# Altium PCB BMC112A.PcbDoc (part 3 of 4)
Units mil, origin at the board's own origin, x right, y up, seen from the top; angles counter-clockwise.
Board outline 5600 x 6100 mil, 8 copper layers (Top Layer, Signal Layer 1, Signal Layer 2, Signal Layer 3, Signal Layer 4, Signal Layer 5, Signal Layer 6, Bottom Layer), stack 62.048 mil thick; 366 components, 158 nets, 872 pads, 1045 vias.
Unrouted connection lines stored in the file: 4.
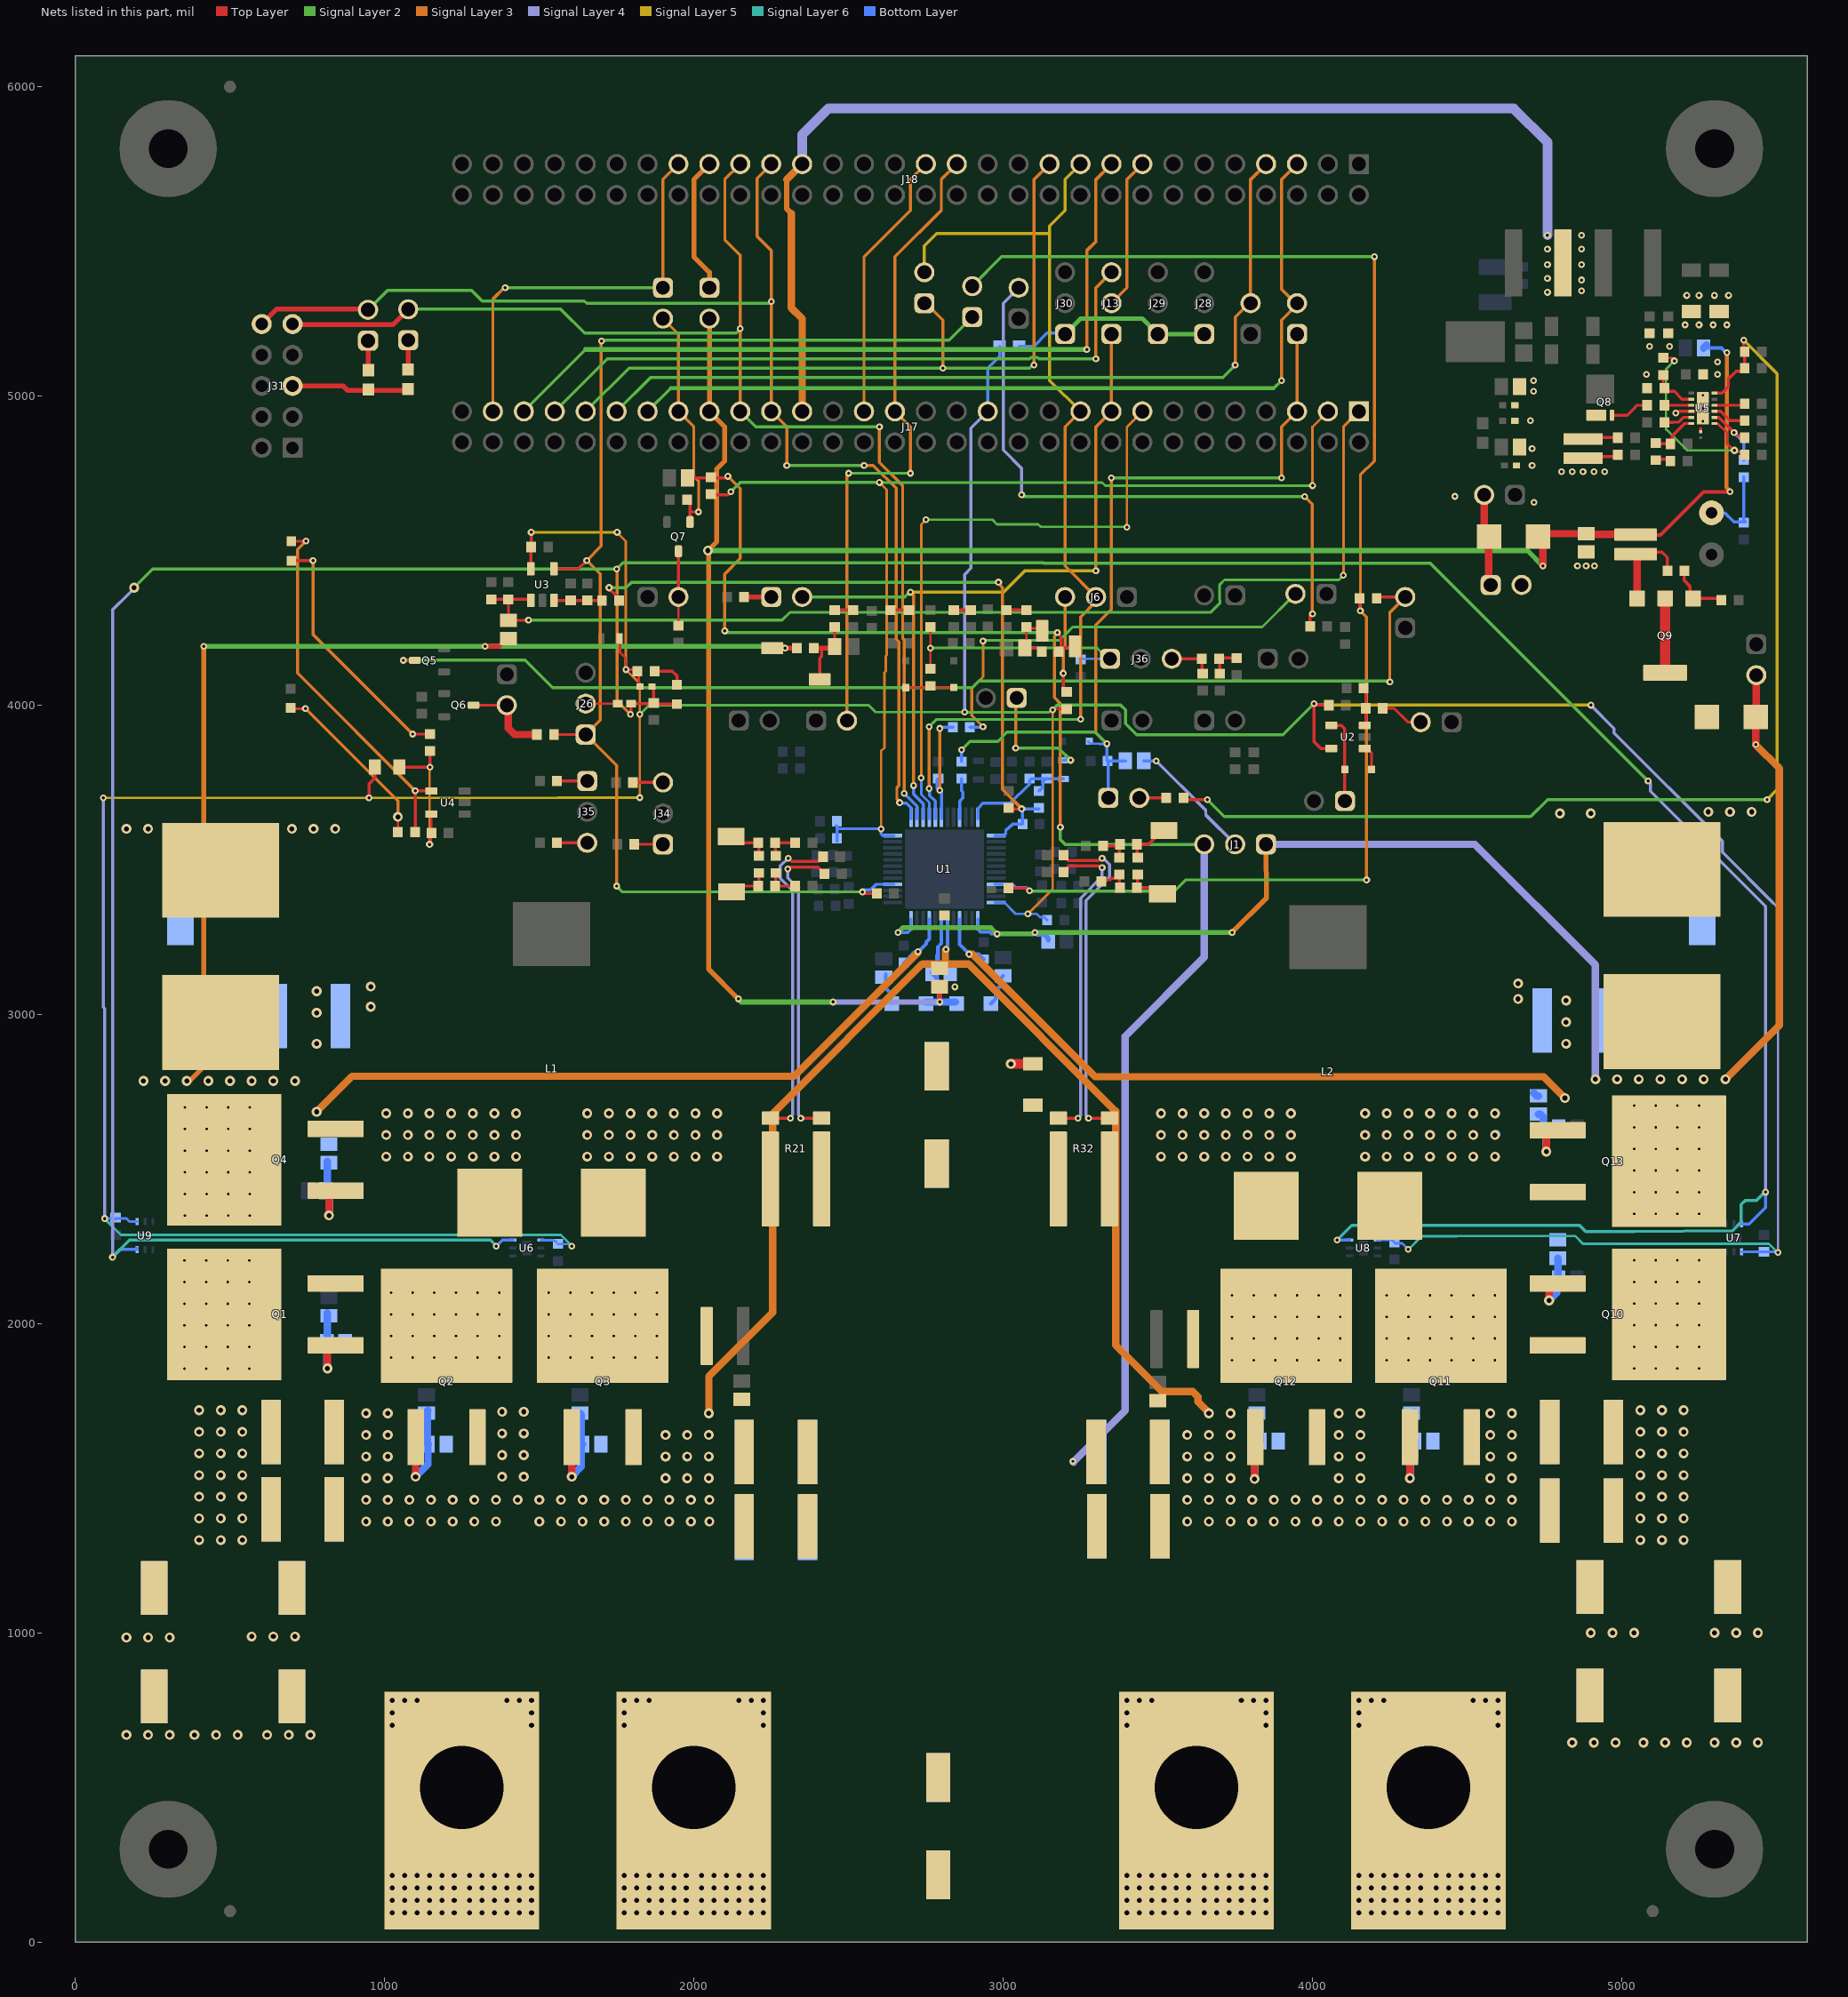
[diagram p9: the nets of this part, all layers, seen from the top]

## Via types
v1: diameter 32, hole 16, Top Layer to Bottom Layer, tented both sides, 330 vias
v2: diameter 32, hole 16, Top Layer to Bottom Layer, 240 vias
v3: diameter 22, hole 10, Top Layer to Bottom Layer, tented both sides, 222 vias
v4: diameter 24, hole 8, Top Layer to Bottom Layer, 192 vias
v5: diameter 19.68, hole 7.87, Top Layer to Bottom Layer, tented both sides, 36 vias
v6: diameter 24, hole 8, Top Layer to Bottom Layer, tented both sides, 14 vias
v7: diameter 24, hole 10, Top Layer to Bottom Layer, tented both sides, 7 vias
v8: diameter 19.68, hole 7.87, Top Layer to Bottom Layer, 3 vias
v9: diameter 22, hole 8, Top Layer to Bottom Layer, tented both sides, 1 vias

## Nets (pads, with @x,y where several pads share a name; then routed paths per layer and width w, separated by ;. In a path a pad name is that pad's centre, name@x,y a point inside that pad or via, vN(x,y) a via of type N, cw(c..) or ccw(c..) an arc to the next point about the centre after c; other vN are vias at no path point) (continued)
NetC76_1: C76.1 R62.1 R69.2 U5.12 | length 3720.2
  Top Layer w9.8: R62.1@3582.56,3700 3587.56,3695 v3(3660,3695) ; U5.12@5299.8,5009.37 5324.37,5009.37 5345,5030 5345,5055 5370,5080 C76.1@5397.44,5080 ; v3(5395,5180) 5395,5141.83 5396.83,5140 R69.2@5400,5140 ; C76.1@5397.44,5077.56 R69.2@5397.44,5130
  Signal Layer 2 w9.8: v3(3660,3695) 3715,3640 4705.47,3640 4760.47,3695 v3(5470,3695)
  Signal Layer 5 w9.8: v3@5391.62,5182.78 5502.5,5071.9 5502.5,3727.5 v3(5470,3695)
NetC77_1: C77.1 U5.9 | length 102.8
  Top Layer w9.8: U5.9@5299.82,4950.29 5319.7,4950.29 5349.99,4920 C77.1@5390,4920
NetC78_1: C78.1 C79.1 U5.6 | length 143.7
  Top Layer w9.8: C78.1@5120,4845 C79.1@5157.44,4845 5163.73,4851.29 5163.73,4870.69 5203.98,4910.94 U5.6@5225,4910.94
NetC78_2: C78.2 R70.2 | length 59.5
  Top Layer w9.8: C78.2@5105,4795 5157.44,4795 R70.2@5152.44,4790
NetC81_1: C81.1 R73.2 | length 61
  Top Layer w10: C81.1@2455,4310 2457.44,4307.56 R73.2@2515,4307.56
NetC81_2: C81.2 R75.2 R77.1 TP2.1 | length 230.5
  Top Layer w8: C81.2@2455,4250 2455,4190.47 R75.2@2455.47,4190
  Top Layer w10: TP2.1@2406.59,4083.27 2406.59,4151.55 2413.31,4158.27 2413.31,4182.03 2416.28,4185
  Top Layer w16: R77.1@2387.56,4185 2416.28,4185 2445,4185 R75.2@2450,4180
NetC82_1: C82.1 R76.1 R78.2 TP3.1 | length 188.7
  Top Layer w8: R76.1@3069.53,4185 3075,4190.47 C82.1@3075,4245 ; C82.1@3075,4252.44 3079.13,4248.31 TP3.1@3137.24,4248.31
  Top Layer w10: R76.1@3070,4185 R78.2@3132.44,4185
NetC82_2: C82.2 R74.1 | length 61.1
  Top Layer w10: R74.1@3010,4307.56 3067.44,4307.56 C82.2@3070,4305
NetC85_1: C85.1 CS1B.1 R93.2 | length 155.2
  Top Layer w10: CS1B.1@2115,3390 2140,3415 R93.2@2207.44,3415 ; R93.2@2210,3405 C85.1@2210,3457.44
NetC85_2: C85.2 CS1A.1 R82.2 | length 135.2
  Top Layer w10: CS1A.1@2120,3575 2140,3555 R82.2@2207.44,3555 ; C85.2@2210,3512.56 2210,3545 R82.2@2215,3550
NetC86_2: C86.2 R83.1 | length 56
  Top Layer w10: R83.1@2640,4310 2642.44,4307.56 C86.2@2695,4307.56
NetC87_2: C87.2 R84.1 | length 56
  Top Layer w12: C87.2@2840,4307.56 2892.56,4307.56 R84.1@2895,4310
NetC88_1: C88.1 R85.1 R92.2 | length 95.5
  Top Layer w10: C88.1@3700,4102.56 3700,4140 R85.1@3705,4145 ; R85.1@3700,4155 3702.44,4152.56 R92.2@3750,4152.56
NetC91_1: C91.1 R89.2 R109.2 U3.3 | length 155.6
  Top Layer w10: U3.3@1547.4,4338.82 1601.4,4338.82 R109.2@1601.63,4338.59 C91.1@1654.93,4338.59 1702.54,4338.59 R89.2@1702.83,4338.3
NetC95_1: C95.1 R87.1 U2.3 | length 114.2
  Top Layer w9: R87.1@4172.44,3990 C95.1@4172.44,4047.56
  Top Layer w10: U2.3@4169.13,3934.69 4172.44,3938 R87.1@4172.44,3990
NetC97_1: C97.1 J36.3 R85.2 | length 150.6
  Top Layer w10: J36.3@3540,4155 J36.3@3545,4150 R85.2@3642.44,4150 3642.44,4107.56 C97.1@3645,4105
NetC98_1: C98.1 CS2B.1 R95.2 | length 133.2
  Top Layer w10: R95.2@3432.56,3410 R95.2@3435,3410 ; C98.1@3435,3452.44 R95.2@3435,3410 ; CS2B.1@3515,3390 3495,3410 R95.2@3435,3410
NetC98_2: C98.2 CS2A.1 R94.2 | length 147.2
  Top Layer w10: C98.2@3435,3510 3432.56,3512.44 R94.2@3432.56,3550 3470,3550 3515.1,3595.1 CS2A.1@3519.9,3595.1 CS2A.1@3520,3595
NetC99_1: C99.1 R93.1 R97.2 | length 122
  Top Layer w10: R93.1@2262.56,3415 R93.1@2265,3415 ; C99.1@2265,3457.44 R93.1@2265,3415 ; R97.2@2340,3410 2335,3415 2332.44,3415 R93.1@2265,3415
NetC99_2: C99.2 R82.1 R96.2 | length 113
  Top Layer w10: C99.2@2270,3510 2262.56,3517.44 R82.1@2262.56,3555 R96.2@2327.44,3555
NetC100_1: C100.1 R95.1 R99.2 | length 91.1
  Top Layer w9.8: R99.2@3317.56,3430 3322.56,3435 3345,3435 3350,3440 C100.1@3360,3440 ; R95.1@3370,3410 3375,3415 C100.1@3375,3452.44
NetC100_2: C100.2 R94.1 R98.2 | length 94.9
  Top Layer w9.8: R98.2@3322.56,3545 R94.1@3375,3545 ; C100.2@3375,3507.56 R94.1@3375,3545 ; R94.1@3375,3550 R94.1@3375,3545
NetC106_1: C106.1 J36.1 R81.1 R86.2 | length 825.5
  Top Layer w8: R81.1@2765,4120 v3(2765,4185) R86.2@2765,4250
  Signal Layer 2 w8: v3(2765,4185) 3303.38,4185 3338.38,4150 J36.1@3345,4150 J36.1@3350,4150
  Bottom Layer w8: C106.1@3250,4147.6 3252.4,4150 J36.1@3345,4150
NetD1_1: D1.1 R13.2 | length 103.2
  Bottom Layer w9.8: D1.1@2637.48,3037.4 D1.1@2639.88,3035
  Bottom Layer w12: R13.2@2620,3130 2620,3085.06 2637.48,3067.58 D1.1@2637.48,3037.4
NetD2_1: D2.1 R19.2 | length 106
  Bottom Layer w12: D2.1@2960.12,3035 2974.98,3049.87 2974.98,3075.5 2990.33,3090.85 2990.33,3115.12 R19.2@2999.78,3124.57
NetD3_2: D3.2 J26.2 | length 103.3
  Top Layer w8: J26.2@1650,4005 D3.2@1753.35,4005
NetD5_2: D5.2 R42.1 | length 108.7
  Top Layer w10: R42.1@1872.56,4110 1930,4110 1945,4095 D5.2@1945,4066.5 D5.2@1945,4065
NetD6_2: D6.2 J38.2 J39.1 | length 291.8
  Top Layer w24: J38.2@4555,4680 4555,4550 D6.2@4565.63,4539.37 ; J39.1@4570,4400 4570,4543.74 D6.2@4571.26,4545
  Top Layer w32: D6.2@4575,4550 D6.2@4576.26,4550
NetD7_1: D7.1 Q9.2 Q9.4 | length 245.1
  Top Layer w32: Q9.4@5140,4100 Q9.4@5140,4104.92 Q9.2@5140,4345.08
NetD9_1: D9.1 D10.1 R81.2 | length 160
  Top Layer w8: D9.1@2685,4056.69 2770,4056.69 D10.1@2845,4056.69
NetD11_2: D11.2 R90.2 | length 566.7
  Top Layer w8: R90.2@1042.91,3589.16 v1(1042.91,3638.91)
  Top Layer w9: D11.2@700.46,3988.84 v3(743.75,3988.84)
  Signal Layer 3 w10: v3@743.87,3988.72 1042.91,3689.68 v1(1042.91,3638.91)
NetD12_1: D12.1 R90.1 U4.4 | length 1206.2
  Top Layer w9: D12.1@701.73,4530.2 701.92,4530.38 v3(745.21,4530.38)
  Top Layer w10: R90.1@1098.03,3589.16 1098.64,3589.78 v3(1098.64,3723.51) 1099.2,3722.96 1150.31,3722.96 U4.4@1150.87,3722.4
  Signal Layer 3 w10: v3(745.21,4530.38) 718.53,4503.7 718.53,4103.63 v3(1098.64,3723.51)
NetD12_2: D12.2 R91.2 | length 819.9
  Top Layer w10: D12.2@698.23,4467.2 v3(768.08,4467.2) ; v3(1090.45,3906.5) R91.2@1146.22,3906.5
  Signal Layer 3 w10: v3(768.08,4467.2) 768.08,4228.86 v3(1090.45,3906.5)
NetD13_1: D13.1 U2.1 | length 80.7
  Top Layer w10: U2.1@4169.13,3859.89 4176.26,3859.89 4191.01,3845.14 D13.1@4191.01,3792.44
NetD13_2: D13.2 J42.1 U2.4 | length 272
  Top Layer w10: U2.4@4060.87,3934.69 4093.28,3934.69 4104.4,3923.58 D13.2@4104.4,3792.44 4104.4,3700.6 J42.1@4105,3700
NetJ1_2: J1.2 R2.2 | length 416.1
  Signal Layer 4 w9.8: v3(3495,3820) 3655,3660 3655,3650
  Signal Layer 4 w10: 3655,3650 3655,3645 J1.2@3750,3550
  Bottom Layer w9.8: R2.2@3454.53,3820 v3(3495,3820)
NetJ3_2: J3.2 Q7.3 R10.1 | length 247.3
  Top Layer w8: R10.1@1950,4257.56 J3.2@1950,4345
  Top Layer w9: Q7.3@1950,4497.76 J3.2@1950,4350 1950,4345 J3.2@1955,4340
NetJ4_2: J4.2 Q6.3 R8.1 | length 282.6
  Top Layer w9.8: Q6.3@1287.24,4000 1390,4000 J4.2@1395,3995
  Top Layer w24: J4.2@1395,3995 1400,3990 1400,3925 1420,3905 R8.1@1492.44,3905
NetJ5_2: J5.2 Q5.3 R1.1 | length 3666.5
  Top Layer w9.8: v3(1060,4145) Q5.3@1097.76,4145 ; R1.1@4207.56,4345 4212.56,4350 4295,4350 J5.2@4300,4345
  Signal Layer 2 w9.8: v3(1060,4145) 1060.25,4145.25 1454.75,4145.25 1543.19,4056.81 2900.43,4056.81 2921.26,4077.64 4238.74,4077.64 4239.04,4077.33 4247.67,4077.33 v3(4250,4075)
  Signal Layer 3 w9.8: v3(4250,4075) 4250,4300 J5.2@4300,4350
NetJ6_3: J6.3 R15.1 | length 314.9
  Top Layer w10: v3(3193.83,4103.31) 3193.83,4053.31 3204.58,4042.56 R15.1@3205,4042.56
  Signal Layer 3 w10: v3(3193.83,4103.31) 3193.83,4183.19 3200,4189.36 J6.3@3200,4350
NetJ12_2: J12.2 R20.2 | length 1426.7
  Signal Layer 2 w9: v3(2935,4207.87) 2937.13,4210 3183.06,4210 3204.84,4231.78 3204.84,4232.47 3225,4252.63 3837.63,4252.63 J12.2@3945,4360
  Signal Layer 3 w9: v3(2935,3930) 2898.33,3966.67 2898.33,4055.28 2935,4091.94 v3(2935,4207.87)
  Bottom Layer w9: R20.2@2892.56,3928.94 2936.06,3928.94 v3(2935,3930)
NetJ13_2: J13.2 J18.15 | length 491.4
  Signal Layer 3 w10: J13.2@3350,5300 3400,5350 3400,5700 J18.15@3450,5750
NetJ13_3: J13.3 J17.53 | length 2125.2
  Signal Layer 2 w10: J17.53@1550,4950 1720,5120 3084.82,5120 3089.7,5124.87 3110.3,5124.87 3115.18,5120 v3(3300,5120)
  Signal Layer 3 w10: v3(3300,5120) 3300,5350 J13.3@3350,5400
NetJ14_2: J14.2 R18.1 | length 2080
  Top Layer w10: R18.1@3992.44,4255 3992.44,4289.14 3998.3,4295 v3(4000,4295)
  Signal Layer 2 w10: v3(3060,4680) 3065,4675 v3(3975,4675)
  Signal Layer 3 w10: v3(3975,4675) 3999.65,4650.35 3999.65,4295.35 v3(4000,4295)
  Signal Layer 4 w10: J14.2@3045,5365 3045,5345 3000,5300 3000,4825 3060,4765 v3(3060,4680)
NetJ16_2: J16.2 J17.31 J18.27 | length 2089
  Signal Layer 2 w9.8: v3(2500,4750) v3(2700,4750)
  Signal Layer 3 w8: J17.31@2650,4950 J17.31@2650,4960
  Signal Layer 3 w9.8: J16.2@2495,3950 2495,4745 v3(2500,4750) ; J17.31@2650,4960 2650,5450 2800,5600 2800,5700 J18.27@2850,5750 ; J17.31@2670,4940 2668.02,4938.02 2668.02,4931.98 2700,4900 v3(2700,4750)
NetJ17_33: J17.33 J18.29 | length 882.8
  Signal Layer 3 w9.8: J17.33@2550,4950 2550,5450 2700,5600 2700,5700 J18.29@2750,5750
NetJ17_47: J17.47 J18.5 J22.2 | length 2853.6
  Signal Layer 2 w10: J17.47@1850,4950 1925,5025 ; 3875,5025 v3(3900,5050)
  Signal Layer 2 w12: 1925,5025 3875,5025
  Signal Layer 3 w10: v3(3900,5050) 3900,5245 3950,5295 3900,5345 3900,5700 J18.5@3950,5750
NetJ17_49: J17.49 J18.7 J23.2 | length 2753.6
  Signal Layer 2 w10: J17.49@1750,4950 1860,5060 3710,5060 v3(3750,5100)
  Signal Layer 3 w10: v3(3750,5100) 3750,5255 3800,5305 3800,5700 J18.7@3850,5750
NetJ17_51: J17.51 J18.21 J32.1 | length 2424.8
  Signal Layer 2 w10: J17.51@1650,4950 1790,5090 v3(2805,5090) 3085,5090 v3@3100,5105
  Signal Layer 3 w10: J32.1@2745,5305 2805,5245 v3(2805,5090) ; v3(3100,5100) 3100,5700 J18.21@3150,5750
NetJ17_55: J17.55 J18.17 | length 2541
  Signal Layer 2 w10: J17.55@1450,4950 1650,5150 ; v3(3270,5150) v3@3275,5150
  Signal Layer 2 w16: 1650,5150 v3(3270,5150)
  Signal Layer 3 w10: v3(3270,5150) 3270,5470 3300,5500 3300,5700 J18.17@3350,5750
NetJ17_57: J17.57 J18.45 J20.1 | length 1349.2
  Signal Layer 2 w10: v3(1390,5350) J20.1@1900,5350
  Signal Layer 3 w9.8: J20.1@1900,5350 1900,5700 J18.45@1950,5750
  Signal Layer 3 w10: J17.57@1350,4950 1350,5313.31 1386.69,5350 v3(1390,5350)
NetJ18_43: J18.43 J19.1 | length 441.4
  Signal Layer 3 w16: J19.1@2050,5350 2050,5400 2000,5450 2000,5700 J18.43@2050,5750
NetJ25_1: J25.1 R101.1 | length 95.4
  Top Layer w16: R101.1@1075.28,5085.4 1075.84,5085.96 1075.84,5179.81 J25.1@1076.4,5180.37
NetJ27_1: J27.1 R17.1 | length 94.5
  Top Layer w10: J27.1@2245,4350 J27.1@2250,4345
  Top Layer w16: R17.1@2162.56,4350 2245,4350 J27.1@2250,4350
NetJ28_1: J28.1 J29.1 J30.1 R105.1 | length 658.7
  Signal Layer 2 w14: J30.1@3200,5200 3250,5250 3450,5250 J29.1@3500,5200 J28.1@3650,5200
  Bottom Layer w10: R105.1@3051.48,5160.84 3099.64,5160.84 3141.81,5203.01 3196.99,5203.01 J30.1@3200,5200
NetJ31_5: J31.5 R101.2 R103.2 | length 380.7
  Top Layer w16: J31.5@702.36,5032.48 865.83,5032.48 880.22,5018.09 1070.96,5018.09 R101.2@1075.28,5022.41
NetJ34_1: J34.1 R44.2 | length 92.4
  Top Layer w9.8: R44.2@1807.56,3550 J34.1@1900,3550
NetJ34_3: J34.3 R55.2 | length 104.5
  Top Layer w9.8: R55.2@1802.56,3750 J34.3@1900,3750 J34.3@1905,3745
NetJ35_1: J35.1 R47.2 | length 99.5
  Top Layer w9.8: R47.2@1557.56,3755 1650,3755 J35.1@1655,3750
NetJ35_3: J35.3 R48.2 | length 99.5
  Top Layer w9.8: R48.2@1557.56,3550 1562.56,3555 J35.3@1655,3555
NetJ37_1: J37.1 R64.1 | length 381.2
  Signal Layer 2 w10: v3(3040.15,3861.11) 3178.82,3861.11 v3(3218.11,3821.81)
  Signal Layer 3 w10: v3(3040.15,3861.11) 3040.15,4019.89 J37.1@3043.56,4023.3
  Bottom Layer w10: R64.1@3194.78,3821.81 v3(3218.11,3821.81)
NetJ40_2: J40.2 R62.2 | length 87.4
  Top Layer w9.8: J40.2@3440,3700 R62.2@3527.44,3700
NetJ43_2: J43.2 R87.2 | length 164.6
  Top Layer w9: R87.2@4227.56,3990 4264.04,3990 4309.29,3944.75 4372.2,3944.75 J43.2@4373.03,3943.92
NetJ44_1: J44.1 R103.1 | length 95.5
  Top Layer w16: J44.1@946.3,5178.58 946.88,5178 946.88,5084.16 R103.1@947.45,5083.59
NetL1_2: L1.2 R21.3 | length 0
  other v1: 1655,2540 1725,2540 1795,2540 1865,2540 1935,2540 2005,2540 2075,2540 1655,2610 1725,2610 1795,2610 1865,2610 1935,2610 2005,2610 2075,2610 1655,2680 1725,2680 1795,2680 1865,2680 1935,2680 2005,2680 2075,2680
NetL2_1: L2.1 R32.4
  other v1: 3510,2540 3580,2540 3650,2540 3720,2540 3790,2540 3860,2540 3930,2540 3510,2610 3580,2610 3650,2610 3720,2610 3790,2610 3860,2610 3930,2610 3510,2680 3580,2680 3650,2680 3720,2680 3790,2680 3860,2680 3930,2680
NetQ1_1: Q1.1 R22.2 R26.2 | length 292
  Top Layer w24: v2(815,1855) 815,1916.08 828.92,1930 Q1.1@841.63,1930
  Bottom Layer w24: R26.2@809.53,1935 R26.2@813.47,1938.94 ; v2(815,1855) 813.47,1856.53 R26.2@813.47,1938.94 ; R26.2@815,1950 R26.2@814.76,1949.76 ; R22.2@815,2035 814.76,2034.76 R26.2@814.76,1949.76 ; R26.2@813.47,1938.94 814.76,1940.24 R26.2@814.76,1949.76 ; R26.2@813.47,1938.94 813.47,1948.47 R26.2@814.76,1949.76
NetQ2_1: Q2.1 R24.1 R27.2 | length 351.3
  Top Layer w24: v2(1100,1505) Q2.1@1100,1632.64
  Bottom Layer w24: v2(1100,1505) 1140,1545 R24.1@1140,1600 ; R27.2@1140,1720 1137.74,1717.74 1137.74,1612.74 R24.1@1140.47,1610
NetQ3_1: Q3.1 R25.1 R28.2 | length 350.6
  Top Layer w24: v2@1600,1505 v2@1602.5,1507.5 ; v2(1605,1505) Q3.1@1605,1632.64
  Bottom Layer w24: v2@1602.84,1505 v2(1605,1505) 1605,1507.16 1635,1537.16 1635,1605 R25.1@1640,1610 ; R28.2@1631.77,1710.47 1636.12,1706.12 1636.12,1616.12 R25.1@1635,1615
NetQ4_1: Q4.1 R29.2 R30.2 | length 266.2
  Top Layer w24: v2(820,2350) 820,2408.37 Q4.1@841.63,2430
  Bottom Layer w24: R30.2@809.53,2430 814.76,2435.24 814.76,2524.76 R29.2@815,2525 ; v2(820,2350) R30.2@820,2430
NetQ8_1-2-3: Q8.1-2-3 R54.1 R60.2 | length 110.2
  Top Layer w9.8: R60.2@4875,4865.51 4984.49,4865.51 R54.1@4985,4865
NetQ8_4: Q8.4 R52.1 | length 134.5
  Top Layer w9.8: 5035,4955 5050,4970 5080,4970 R52.1@5085,4965 ; R52.1@5082.44,4970 R52.1@5085,4970
  Top Layer w10: Q8.4@4968.39,4937.91 5017.91,4937.91 5035,4955
NetQ9_1: Q9.1 R71.1 R72.2 | length 197.9
  Top Layer w10: R72.2@5202.56,4435 5202.56,4402.44 5220,4385 5220,4350 Q9.1@5230,4340 ; Q9.1@5230.55,4345.08 5314.92,4345.08 R71.1@5320,4340
NetQ9_3: Q9.3 R68.2 R72.1 | length 257.5
  Top Layer w10: R68.2@5085,4495 5130,4495 5147.44,4477.56 R72.1@5147.44,4435
  Top Layer w24: R68.2@5045,4488.5 5049.45,4484.06 Q9.3@5049.45,4345.08
NetQ10_1: Q10.1 R33.1 R37.2 | length 223.3
  Top Layer w24: v2(4765,2075) 4765,2113.94 4781.06,2130 Q10.1@4792.64,2130
  Bottom Layer w24: v2(4765,2075) 4789.17,2099.17 4789.17,2138.7 R37.2@4795.47,2145 4794.33,2146.14 4794.33,2210.35 R33.1@4793.19,2211.49
NetQ11_1: Q11.1 R35.1 R38.2 | length 365.1
  Top Layer w24: v2(4315,1500) Q11.1@4315,1632.64
  Bottom Layer w24: v2(4315,1500) 4316.53,1501.53 4316.53,1546.53 4330,1560 4330,1620 R35.1@4325,1625 ; R38.2@4330,1715 4325.24,1710.24 4325.24,1625.24 R35.1@4330.47,1620
NetQ12_1: Q12.1 R36.1 R39.2 | length 345.5
  Top Layer w24: v2(3812.69,1497.72) 3812.69,1630.33 Q12.1@3815,1632.64
  Bottom Layer w24: v2(3812.69,1497.72) 3812.69,1556.29 3820,1563.6 R36.1@3820,1620 ; R39.2@3820,1700 3830.47,1689.53 R36.1@3830.47,1620
NetQ13_1: Q13.1 R40.1 R41.2 | length 271.5
  Top Layer w24: v2(4756,2556.42) 4756,2604.49 4776.52,2625 Q13.1@4792.64,2625
  Bottom Layer w24: R40.1@4730.67,2677.3 4736.58,2677.3 4746.23,2667.64 4746.23,2637.35 4752.6,2630.98 ; v2(4756,2556.42) 4756,2627.58 4752.6,2630.98 ; R41.2@4795.47,2632.44 4794.02,2630.98 4752.6,2630.98
NetR7_1: R7.1 U1.45 | length 134.9
  Bottom Layer w9.8: U1.45@2859.21,3632.4 2859.21,3689.53 2868.77,3699.09 ; R7.1@2865,3762.44 2865,3723.62 2869.84,3718.78 2869.84,3700.16
NetR21_1: R21.1 R56.2 | length 1060
  Top Layer w9.8: v3(2305,3505) 2306.17,3505 2316.84,3494.33 2402.76,3494.33 2417.44,3509.02 R56.2@2417.44,3510
  Top Layer w10: R21.1@2247.43,2664.48 v3@2311.89,2664.48
  Signal Layer 4 w9.8: v3(2305,3505) 2304.27,3505 2279.43,3480.15 2279.43,3440.58 2319.84,3400.17 2319.84,2676.21 2317.99,2674.36 2317.99,2673.77 2311.89,2667.67 v3@2311.89,2664.48
  other v3: 2311.89,2664.37
NetR21_2: R21.2 R57.2 | length 1019.1
  Top Layer w9.8: v3(2303.2,3470.31) 2306.5,3470.31 2312.85,3476.66 2401.77,3476.66 2418.43,3460 R57.2@2422.44,3460
  Top Layer w10: v3@2345.7,2664.48 R21.2@2412.57,2664.48
  Signal Layer 4 w9.8: v3(2303.2,3470.31) 2303.2,3441.8 2337.51,3407.49 2337.51,2676.21 2339.6,2674.12 2339.6,2673.77 2345.7,2667.67 v3@2345.7,2664.48
  other v3: 2345.7,2664.37
NetR32_1: R32.1 R59.2 | length 1036.9
  Top Layer w10: R32.1@3177.43,2664.37 v3(3241.89,2664.37) ; R59.2@3199.13,3465 3214.53,3480.4 3311.35,3480.4 3316.75,3475 v3(3320,3475)
  Signal Layer 4 w9.8: v3(3241.89,2664.37) 3249.95,2672.43 3249.95,3375.55 3320,3445.61 v3(3320,3475)
NetR32_2: R32.2 R58.2 | length 1089.2
  Top Layer w10: R58.2@3195.12,3515 3195.12,3514.02 3210.86,3498.27 3310.03,3498.27 3316.75,3505 v3(3320,3505) ; v3(3275.7,2664.37) R32.2@3342.57,2664.37
  Signal Layer 4 w10: v3(3275.7,2664.37) 3267.72,2672.35 3267.72,3368.19 3343.87,3444.34 3343.87,3484.89 3329.89,3498.87 3329.37,3498.87 3324.07,3504.18 v3@3320.11,3504.18
NetR52_2: R52.2 U5.3 | length 100
  Top Layer w9.8: R52.2@5130,4970 R52.2@5137.56,4970 ; R52.2@5132.56,4970 U5.3@5225,4970
NetR53_2: R53.2 U5.5 | length 91.5
  Top Layer w9: 5165,4915 5183.61,4915 5199.24,4930.63 U5.5@5225,4930.63
  Top Layer w9.8: R53.2@5140,4915 5165,4915
NetR63_1: R63.1 R65.2 TP6.1 | length 269.1
  Bottom Layer w10: TP6.1@5290,4622 5333,4622 5362.44,4592.56 5395,4592.56 5400,4592.56 5395,4597.56 R65.2@5395,4737.44
NetR65_1: R65.1 R66.2 U5.8 | length 223.9
  Top Layer w9.8: U5.8@5299.82,4930.61 5314.39,4930.61 v3(5363.58,4881.42) 5372.73,4872.27 5389.83,4872.27 R66.2@5395.38,4866.72
  Bottom Layer w10: v3(5363.58,4881.42) 5395,4850 R65.1@5395,4792.56
NetR67_2: R67.2 U5.10 | length 102.3
  Top Layer w9.8: U5.10@5299.8,4970 5395,4970 R67.2@5400,4975
NetR104_1: R104.1 R107.2 U5.7 | length 678.4
  Top Layer w8: R107.2@5134.09,5123.19 5162.62,5123.19 5169.77,5116.04 v7(5169.77,5113.39) ; U5.7@5299.8,4910.94 5300.72,4910.02 5311.25,4910.02 5340.16,4881.12 5340.16,4846.41 5362.81,4823.77 5363.37,4824.33 v7(5364.58,4824.33) ; v7@5368.27,4818.31 5385.69,4818.31 5397.44,4806.56 R104.1@5397.44,4806.38
  Signal Layer 2 w8: v7(5169.77,5113.39) 5143.32,5086.94 5143.32,4892.31 5211.3,4824.33 v7(5364.58,4824.33)
OPT: J6.2 J17.19 J18.19 J32.2 U1.41 | length 3275.8
  Signal Layer 2 w9.8: v3(2760,3930) 2783.77,3953.77 3248.77,3953.77 v3(3250,3955)
  Signal Layer 3 w9.8: v3(2760,3730) v3(2760,3930) ; v3(3250,3955) 3250,4285.07 J6.2@3300,4335.07 ; J17.19@3250,4950 3200,4900 3200,4450 J6.2@3300,4350 3305,4345 J6.2@3305,4340
  Signal Layer 5 w9.8: J32.2@2745,5400 2745,5485 2785,5525 3150,5525 ; J17.19@3250,4950 3150,5050 3150,5525 ; J18.19@3250,5750 3200,5700 3200,5600 3150,5550 3150,5525
  Bottom Layer w9.8: v3@2760,3725 v3(2760,3730) 2762.33,3727.67 2762.33,3707.75 2780.47,3689.61 U1.41@2780.47,3632.4
OSC: R16.2 R20.1 U1.42 | length 379.2
  Signal Layer 3 w10: v3(2795,3725) v3(2795,3925)
  Bottom Layer w10: R16.2@2790,3762.44 2786.81,3759.25 2786.81,3732.49 2794.29,3725 v3(2795,3725) ; v3(2795,3925) 2798.25,3925 2802.18,3928.94 R20.1@2837.44,3928.94 ; U1.42@2800.16,3632.4 v3@2800.16,3725
OTEMP: C102.1 D3.1 D5.1 R102.1 U6.3 U7.3 U8.3 U9.3 | length 12756.7
  Top Layer w10: v3(1795,3970) 1796.65,3971.65 D3.1@1796.65,4005 1870,4005 1871.5,4003.5 D5.1@1945,4003.5 ; C102.1@1870,4007.56 R102.1@1870,4060
  Signal Layer 2 w10: v1(190,4380) 250,4440 v3(1750,4440) 1770,4460 3130,4460 3130.82,4459.18 4380.82,4459.18 v3(5085,3755)
  Signal Layer 3 w10: v3(1750,4440) 1751.25,4438.75 1751.25,4013.75 v3(1795,3970)
  Signal Layer 4 w10: v3(120,2215) 120,4308 172,4360 v1@198,4386 ; v3(5085,3755) 5092.8,3747.2 5092.8,3722.2 5465,3350 v3(5465,2425)
  Signal Layer 6 w10: v3(120,2215) 174.81,2270 1342.4,2270 v3@1365.74,2246.66 ; v3(4080,2270) 4127.17,2317.37 4863.68,2317.37 4883.68,2297.37 5041.3,2297.37 5041.4,2297.37 5358.23,2300.65 5386.13,2328.55 5386.13,2384.89 5400.11,2398.87 5435.85,2398.87 v3@5463.22,2426.24
  Bottom Layer w10: v3(120,2215) 144.72,2239.72 U9.3@199.41,2239.72 199.41,2244.92 U9.3@199.33,2245 ; v3(1360.79,2250) 1380.79,2270 1385,2270 ; 1385.59,2270.59 U6.3@1414.72,2270.59 ; v3(4080,2270) 4106,2270 4106.51,2270.51 4119.65,2270.51 U8.3@4119.72,2270.59 ; U7.3@5388.03,2321.7 5411.7,2321.7 5465,2375 v3(5465,2425)
PGND: C13.2 C18.2 C19.2 C20.2 C21.2 C22.2 C23.2 C24.2 C25.2 C26.2 C27.2 C28.2 C29.2 C31.1 C32.2 C33.2 C40.2 C42.2 C43.2 C44.1 C45.1 C48.1 C49.1 C50.2 C51.2 C52.2 C53.2 C54.2 C55.2 C56.2 C57.2 C58.2 C59.2 C60.2 C61.2 C62.2 C63.2 C64.2 C65.2 C66.2 C67.2 C68.2 C69.2 C70.2 C71.2 C72.2 C73.2 C74.1 C80.2 C104.2 C105.2 C107.2 J10.1 J11.1 J17.37 J18.37 J39.2 L4.2 NT1.2 NT2.1 Q2.3 Q3.3 Q11.3 Q12.3 R24.2 R25.2 R35.2 R36.2 R60.1 R106.1 T3.1 T4.1 U1.18 U5.4 U5.13 | length 7882.5
  Top Layer w9.8: R60.1@4875,4804.49 4994.49,4804.49 C73.2@4995,4805 ; v3(5175,4945) 5178.84,4945 5184.16,4950.32 U5.4@5225,4950.32 5249.68,4950.32 U5.13@5250,4950 ; NT2.1@5255,4885 5255,4895
  Top Layer w32: v1(3025,2840) C31.1@3102.91,2840
  Signal Layer 3 w18: 2300,5700 2300,5605 2315,5590
  Signal Layer 3 w24: v1(2048.24,1710) 2048.24,1829.58 2255,2036.34 2255,2679.41 2738.54,3162.95 2813.04,3162.95 ; 2300,5700 J18.37@2350,5750 ; 2315,5590 2315,5285 2350,5250 J17.37@2350,4950 ; v3(2815,3210) 2813.04,3208.04 2813.04,3162.95 ; v1(3665,1710) 3665,1712.16 3630.2,1746.96 3630.2,1763.03 3613.23,1780 3513.9,1780 3363.51,1930.39 3363.51,2686.98 2887.53,3162.95 2813.04,3162.95
  Signal Layer 4 w32: J18.37@2350,5750 2350,5845 2435,5930 4650,5930 4760,5820 v3(4760,5520)
  Signal Layer 5 w18: v1@4817.9,2977.1 v1(4820,2975)
  Bottom Layer w10: v3@2810,3210 v3@2810,3213.25 ; v3(2815,3210) v3@2819.84,3214.84
  Bottom Layer w11: v3@2819.84,3214.84 U1.18@2819.84,3302.68
  other v1: 4840,645 4910,645 4980,645 5070,645 5140,645 5210,645 5300,645 5370,645 5440,645 165,670 235,670 305,670 385,670 455,670 525,670 620,670 690,670 760,670 940,1360 1010,1360 1080,1360 1150,1360 1220,1360 1290,1360 1360,1360 1500,1360 1570,1360 1640,1360 1710,1360 1780,1360 1850,1360 1920,1360 1990,1360 2050,1360 3595,1360 3665,1360 3735,1360 3805,1360 3875,1360 3945,1360 4015,1360 4085,1360 4155,1360 4225,1360 4295,1360 4365,1360 4435,1360 4505,1360 4575,1360 4645,1360 940,1430 1010,1430 1080,1430 1150,1430 1220,1430 1290,1430 1360,1430 1430,1430 1500,1430 1570,1430 1640,1430 1710,1430 1780,1430 1850,1430 1920,1430 1990,1430 2050,1430 3595,1430 3665,1430 3735,1430 3805,1430 3875,1430 3945,1430 4015,1430 4085,1430 4155,1430 4225,1430 4295,1430 4365,1430 4435,1430 4505,1430 4575,1430 4645,1430 940,1500 1010,1500 1908.24,1500 1978.24,1500 2048.24,1500 3595,1500 3665,1500 3735,1500 4085,1500 4155,1500 4575,1500 4645,1500 1380,1505 1450,1505 940,1570 1010,1570 1908.24,1570 1978.24,1570 2048.24,1570 3595,1570 3665,1570 3735,1570 4085,1570 4155,1570 4575,1570 4645,1570 1380,1575 1450,1575 940,1640 1010,1640 1908.24,1640 1978.24,1640 2048.24,1640 3595,1640 3665,1640 3735,1640 4085,1640 4155,1640 4575,1640 4645,1640 1380,1645 1450,1645 940,1710 1010,1710 3735,1710 4085,1710 4155,1710 4575,1710 4645,1710 1380,1715 1450,1715 780,2905 4820,2905 780,3005 955,3025 4820,3045 4665,3050 780,3075 955,3090 4665,3100 165,3600 235,3600 700,3600 770,3600 840,3600 4800,3650 4900,3650 5280,3655 5350,3655 5420,3655
  other v2: 1775,95 1815,95 1855,95 1895,95 1935,95 1975,95 2025,95 2065,95 2105,95 2145,95 2185,95 2225,95 4150,95 4190,95 4230,95 4270,95 4310,95 4350,95 4400,95 4440,95 4480,95 4520,95 4560,95 4600,95 1775,135 1815,135 1855,135 1895,135 1935,135 1975,135 2025,135 2065,135 2105,135 2145,135 2185,135 2225,135 4150,135 4190,135 4230,135 4270,135 4310,135 4350,135 4400,135 4440,135 4480,135 4520,135 4560,135 4600,135 1775,175 1815,175 1855,175 1895,175 1935,175 1975,175 2025,175 2065,175 2105,175 2145,175 2185,175 2225,175 4150,175 4190,175 4230,175 4270,175 4310,175 4350,175 4400,175 4440,175 4480,175 4520,175 4560,175 4600,175 1775,215 1815,215 1855,215 1895,215 1935,215 1975,215 2025,215 2065,215 2105,215 2145,215 2185,215 2225,215 4150,215 4190,215 4230,215 4270,215 4310,215 4350,215 4400,215 4440,215 4480,215 4520,215 4560,215 4600,215 1775,701.27 2225,701.27 4150,701.27 4600,701.27 1775,741.27 2225,741.27 4150,741.27 4600,741.27 1775,781.27 1815,781.27 1855,781.27 2145,781.27 2185,781.27 2225,781.27 4150,781.27 4190,781.27 4230,781.27 4520,781.27 4560,781.27 4600,781.27
  other v3: 2843.59,3088.95 4856.46,4450 4885,4450 4911.3,4450.45 4716.54,4655.51 4460.08,4675.27 4805,4755 4840,4755 4875,4755 4910,4755 4945,4755 4710,4775 4710,4830 4705,4920 4715,5015 4715,5050 5080,5070 5310,5070 5310,5110 5090,5160 5155,5160 5205,5230 5250,5230 5295,5230 5340,5230 5210,5325 5250,5325 5300,5325 5345,5325 4760,5335 4870,5340 4870,5375 4760,5380 4760,5425 4870,5425 4760,5475 4870,5475 4870,5520
  other v8: 5262.4,4917.83 5262.4,4960.16 5262.4,5002.48
SCL: J17.41 J18.41 J25.2 J31.9 U1.38 | length 4151.6
  Top Layer w16: J31.9@702.36,5232.48 704.62,5230.22 1026.25,5230.22 J25.2@1076.4,5280.37
  Signal Layer 2 w9.8: J17.41@2145,4950 J17.41@2150,4950 2200,4900 v3(2600,4900)
  Signal Layer 2 w10: J25.2@1076.4,5280.37 1569.66,5280.37 1647.02,5203.01 2137.17,5203.01 2150,5215.84 v3(2150,5217.77)
  Signal Layer 3 w9.8: J18.41@2145,5760 2145,5745 2100,5700 2100,5505 2150,5455 v3(2150,5217.77) J17.41@2150,4950 ; v3(2600,4900) 2600,4785 2675,4710 2675,4216.65 2680,4211.65 v3(2680,3715)
  Bottom Layer w9.8: v3(2680,3715) 2721.42,3673.58 U1.38@2721.42,3632.4
SD_CMD: J17.45 J20.2 Q7.1 R5.2 | length 793.1
  Top Layer w9: R5.2@1980,4670 1987.4,4662.6 1987.4,4630 ; Q7.1@1987.4,4592.24 1987.4,4630 ; v3(2015,4625) 1992.4,4625 1987.4,4630
  Signal Layer 3 w9: J20.2@1900,5260 J20.2@1900,5250 1950,5200 J17.45@1950,4950 2000,4900 2000,4740 2015,4725 v3(2015,4625)
SDA: J17.39 J18.39 J31.10 J44.2 U1.37 | length 4229.3
  Top Layer w16: J31.10@602.36,5232.48 650.72,5280.83 944.04,5280.83 J44.2@946.3,5278.58
  Signal Layer 2 w9.8: v3(2300,4775) v3(2550,4775)
  Signal Layer 2 w10: J44.2@946.3,5278.58 1009.53,5341.81 1280.96,5341.81 1315.48,5307.29 1645.25,5307.29 1653.36,5299.19 2244.19,5299.19 v3(2250,5305)
  Signal Layer 3 w9.8: J18.39@2245,5740 2240,5740 2204.06,5704.06 2204.06,5515.94 2250,5470 v3(2250,5305) J17.39@2250,4950 2300,4900 v3(2300,4775) ; v3(2550,4775) 2580,4775 2653.66,4701.34 2653.66,4212.99 2662.33,4204.33 2662.33,3740 2656.23,3733.9 2656.23,3697.08 2665,3688.3 v3(2665,3685)
  Bottom Layer w9.8: v3(2665,3685) 2667.33,3682.67 2687.33,3682.67 2701.73,3668.27 U1.37@2701.73,3632.4
SS/DEM1: C16.1 J15.1 J26.1 R8.2 U1.28 U3.4 | length 4264.5
  Top Layer w9.8: U3.4@1547.4,4441.18 1626.65,4441.18 v3(1653.36,4467.89) ; R8.2@1547.56,3905 J26.1@1650,3905
  Top Layer w10: v3(2545,3396.23) 2548.25,3396.23 2552.67,3391.81 C16.1@2591.5,3391.81
  Signal Layer 2 w9.8: v3@1700.66,5180 1701.13,5179.53 1712.35,5179.53 1712.82,5180 2825,5180 J15.1@2900,5255 ; v3(1750,3415) 1768.77,3396.23 v3(2545,3396.23)
  Signal Layer 3 w9.8: J26.1@1650,3905 1652.5,3907.5 1696.92,3951.92 1696.92,4424.32 v3(1653.36,4467.89) 1700,4514.53 v3@1700,5177.5 ; J26.1@1655,3905 1655,3900 1750,3805 v3(1750,3415)
  Bottom Layer w9.8: v3@2550.74,3402.33 2570.94,3402.33 2589.4,3420.79 U1.28@2647.6,3420.79
  other v3: 1701.39,5177.2
SS/DEM2: C1.1 J15.2 R1.2 U1.9 | length 4742.1
  Top Layer w9.8: R1.2@4152.44,4345 4152.44,4307.56 v3(4155,4305)
  Top Layer w10: C1.1@3016.8,3408.81 3072.95,3408.81 3081.75,3400 v3(3085,3400)
  Signal Layer 2 w9.8: J15.2@2890,5340 2890,5345 J15.2@2900,5355 2995,5450 v3(4200,5450) ; v3@3085,3405 3085,3404.69 3090.64,3399.06 3554.06,3399.06 3590,3435 v3(4175,3435)
  Signal Layer 3 w9.8: v3(4175,3435) 4175,4285 v3(4155,4305) 4155,4745 4200,4790 v3(4200,5450)
  Bottom Layer w9.8: U1.9@2972.4,3420.79 3029.41,3420.79 3039.47,3410.73 3073.16,3410.73 3083.89,3400 v3(3085,3400)
SW1: C11.2 L1.1 Q1.3 Q2.4 Q3.4 Q4.3 R23.2 R26.1 R29.1 U1.21 | length 2339.3
  Signal Layer 3 w24: v1(780,2685) 895,2800 2323.66,2800 v3@2725,3201.34
  Bottom Layer w10: C11.2@2678.98,3167.57 2713.85,3202.44 v3(2725,3202.44)
  Bottom Layer w11: v3(2725,3202.44) 2750.84,3228.28 2750.84,3234.1 2760.79,3244.05 U1.21@2760.79,3307.6
  other v1: 1005,2540 1075,2540 1145,2540 1215,2540 1285,2540 1355,2540 1425,2540 1005,2610 1075,2610 1145,2610 1215,2610 1285,2610 1355,2610 1425,2610 1005,2680 1075,2680 1145,2680 1215,2680 1285,2680 1355,2680 1425,2680
  other v4: 1020.63,1889.92 1090.63,1889.92 1160.63,1889.92 1230.63,1889.92 1300.63,1889.92 1370.63,1889.92 1530.63,1889.92 1600.63,1889.92 1670.63,1889.92 1740.63,1889.92 1810.63,1889.92 1880.63,1889.92 1020.63,1959.92 1090.63,1959.92 1160.63,1959.92 1230.63,1959.92 1300.63,1959.92 1370.63,1959.92 1530.63,1959.92 1600.63,1959.92 1670.63,1959.92 1740.63,1959.92 1810.63,1959.92 1880.63,1959.92 1020.63,2029.92 1090.63,2029.92 1160.63,2029.92 1230.63,2029.92 1300.63,2029.92 1370.63,2029.92 1530.63,2029.92 1600.63,2029.92 1670.63,2029.92 1740.63,2029.92 1810.63,2029.92 1880.63,2029.92 1020.63,2099.92 1090.63,2099.92 1160.63,2099.92 1230.63,2099.92 1300.63,2099.92 1370.63,2099.92 1530.63,2099.92 1600.63,2099.92 1670.63,2099.92 1740.63,2099.92 1810.63,2099.92 1880.63,2099.92
SW2: C17.2 L2.2 Q10.3 Q11.4 Q12.4 Q13.3 R33.2 R34.2 R40.2 U1.16 | length 2325.2
  Signal Layer 3 w24: v3(2890.14,3195) 2890.31,3194.83 2900.73,3194.83 3297.25,2798.31 4747.42,2798.31 v1(4816.2,2729.54)
  Bottom Layer w11: U1.16@2859.21,3307.6 2859.21,3225.93 2867.44,3217.7 v3(2890.14,3195)
  Bottom Layer w12: v3(2890.14,3195) 2920.64,3195 C17.2@2936.97,3178.67
  Bottom Layer w24: v1(4590,2610) 4592.16,2610 v1@4596.13,2613.97 ; R40.2@4715.11,2746.01 4724.77,2736.35 R40.2@4730.67,2736.35
  other v1: 4170,2540 4240,2540 4310,2540 4380,2540 4450,2540 4520,2540 4590,2540 4170,2610 4240,2610 4310,2610 4380,2610 4450,2610 4520,2610 4170,2680 4240,2680 4310,2680 4380,2680 4450,2680 4520,2680 4590,2680
  other v4: 3740,1881.81 3810,1881.81 3880,1881.81 3950,1881.81 4020,1881.81 4090,1881.81 4240,1881.81 4310,1881.81 4380,1881.81 4450,1881.81 4520,1881.81 4590,1881.81 3740,1951.81 3810,1951.81 3880,1951.81 3950,1951.81 4020,1951.81 4090,1951.81 4240,1951.81 4310,1951.81 4380,1951.81 4450,1951.81 4520,1951.81 4590,1951.81 3740,2021.81 3810,2021.81 3880,2021.81 3950,2021.81 4020,2021.81 4090,2021.81 4240,2021.81 4310,2021.81 4380,2021.81 4450,2021.81 4520,2021.81 4590,2021.81 3740,2091.81 3810,2091.81 3880,2091.81 3950,2091.81 4020,2091.81 4090,2091.81 4240,2091.81 4310,2091.81 4380,2091.81 4450,2091.81 4520,2091.81 4590,2091.81
SYNCIN: J17.15 U1.40 | length 2045.6
  Signal Layer 2 w8: v3(2750,4600) 2965,4600 2980,4585 3113.3,4585 3121.17,4577.13 3397.87,4577.13 v3(3400,4575)
  Signal Layer 3 w8: v3(2735,3765) 2735,4585 v3(2750,4600) ; v3(3400,4575) 3400,4900 J17.15@3450,4950 J17.15@3450,4955
  Bottom Layer w8: v3(2735,3765) 2735,3711.36 2757.98,3688.38 2757.98,3688.08 2760.79,3685.26 U1.40@2760.79,3632.4
SYNCOUT: J13.1 J17.17 J27.2 U1.39 | length 2522.6
  Signal Layer 2 w10: J27.2@2345,4355 J27.2@2350,4350 2681.75,4350 2696.75,4365 v3(2700,4365)
  Signal Layer 3 w10: v3(2700,4365) 2710,4355 v3(2710,3740) ; v3(3300,4435) 3300,4900 J17.17@3350,4950 ; J17.17@3350,4955 J13.1@3350,5200
  Signal Layer 5 w10: v3(2700,4365) 3000,4365 3070,4435 v3(3300,4435)
  Bottom Layer w10: v3(2710,3740) 2710,3712.5 2741.1,3681.39 U1.39@2741.1,3632.4
UVLO: D8.1 J17.5 J22.1 J40.1 R2.1 R6.2 R7.2 | length 2767.4
  Signal Layer 2 w10: v3(2865,3855) 2893.19,3883.19 2982.69,3883.19 3011.98,3912.48 3297.52,3912.48 v3(3335,3875) ; v3(3350,4735) v3(3900,4735)
  Signal Layer 3 w10: v3(3335,3875) 3299.65,3910.35 3299.65,4259.65 3350,4310 v3(3350,4735) ; v3(3900,4735) 3900,4900 J17.5@3950,4950 J22.1@3950,5195
  Bottom Layer w8: D8.1@3275.12,3882.13 3281.86,3875.38 3311.62,3875.38 3312,3875 v3(3335,3875)
  Bottom Layer w10: R7.2@2865,3817.56 v3(2865,3855) ; v3(3335,3875) 3335,3822.56 R6.2@3337.56,3820 ; J40.1@3340,3700 3340,3820 R2.1@3395.47,3820
V5.0: C15.1 C89.1 C90.2 C92.1 C94.2 C101.1 C103.1 J17.25 R15.2 R42.2 R102.2 R105.2 R108.2 R110.2 U1.12 U2.5 U3.5 U6.4 U7.4 U8.4 U9.4 | length 15538.6
  Top Layer w8: R108.2@1757.56,4215.14 1761.3,4211.4 1761.3,4170.45 1780,4151.75 v3(1780,4115) R42.2@1820,4115 ; R102.2@1821.38,4060 1821.38,4101.38 R42.2@1825,4105 ; v3(3160,3985) 3162.44,3987.44 R15.2@3205,3987.44
  Top Layer w10: v3(949.16,3700) 949.16,3745.24 968.55,3764.64 R110.2@968.55,3800 ; U3.5@1472.6,4441.18 1472.6,4510.39 C94.2@1473.74,4511.54 v7(1473.74,4558.97) ; C90.2@4050,4000 4010,4000 v3(4005,4005) 4005,3881.95 4027.06,3859.89 U2.5@4060.87,3859.89
  Signal Layer 2 w8: v3(1825,3970) 1855,4000 2565,4000 2587.31,3977.69 v3(2874.96,3977.69) ; v3@2875.37,3977.29 3148.5,3977.29 3156.21,3985 v3(3160,3985)
  Signal Layer 2 w10: v3(3160,3985) 3175,4000 3380,4000 3395.35,3984.65 3395.35,3940.51 3431.21,3904.65 3904.65,3904.65 v3(4005,4005)
  Signal Layer 3 w8: v7(1751.25,4558.97) 1780,4530.22 v3(1780,4115) 1825,4070 v3(1825,3970) v3(1825,3700.98) v3@1825,3700 ; v3@3084.57,3325.43 3084.57,3329.57 3160,3405 v3(3160,3985)
  Signal Layer 4 w8: 5490,3360 5505,3345 v3(5505,2230)
  Signal Layer 4 w10: v3(90,3700) 90,3023.76 95.22,3018.54 v3@95.22,2340.22 ; v3(2874.96,3977.69) 2874.96,4422.52 2895.35,4442.92 2895.35,4895.35 J17.25@2950,4950 ; v3(4900,4000) 4975,3925 4975,3910 5325,3560 5325,3525 5490,3360
  Signal Layer 5 w8: v3(90,3700) 1558.58,3700 1559.56,3700.98 v3(1825,3700.98) ; v7(1473.74,4558.97) v7(1751.25,4558.97)
  Signal Layer 5 w10: v3(4005,4005) 4008.25,4005 4013.25,4000 v3(4900,4000)
  Signal Layer 6 w8: v3@93.19,2340.75 147.06,2286.87 1570.24,2286.87 v3@1607.41,2249.7 ; v3(4310,2240) 4352.63,2282.63 4466.99,2282.63 4467.99,2283.63 4848.99,2283.63 4874.46,2258.15 5476.06,2258.15 v3@5504.21,2230
  Bottom Layer w8: v3(95,2340) 127.56,2340 C89.1@130,2337.56 ; C89.1@130,2340 165,2340 174.72,2330.28 U9.4@199.41,2330.28 ; U6.4@1505,2270 1546.57,2270 1551.57,2265 C92.1@1555,2265 ; C92.1@1560,2257.56 1597.44,2257.56 v3(1605,2250) ; U1.12@2972.4,3361.73 U1.12@2977.32,3361.73 3004.02,3361.73 3040.76,3325 v3(3080,3325) 3108.38,3325 3118.63,3314.75 3132.69,3314.75 C15.1@3142.44,3305 ; U8.4@4210,2270 4210.59,2270.59 4256.97,2270.59 C103.1@4265,2262.56 4267.56,2260 4290,2260 v3(4310,2240) ; U7.4@5387.93,2232.44 C101.1@5457.44,2232.44 ; C101.1@5460,2232.44 v3@5502.56,2232.44
  Bottom Layer w10: J17.25@2950,4950 2950,5089.7 2988.49,5128.19 R105.2@2988.49,5160.84
V5A: C93.2 R91.1 R110.1 U4.5 | length 501.1
  Top Layer w8: v7(1145.02,3550) 1148.47,3553.44 1148.47,3588.78 1150.87,3591.18 U4.5@1150.87,3647.6
  Top Layer w10: R110.1@1047.29,3800 1048.08,3799.22 v3(1146.22,3799.22) R91.1@1146.22,3851.38
  Signal Layer 3 w8: v7(1145.02,3550) 1145.02,3798.02 v3(1146.22,3799.22)
V10: C13.1 C80.1 C107.1 D1.2 D2.2 D6.1 J17.43 J19.2 R61.2 R68.1 U1.19 | length 7483.4
  Top Layer w12: R68.1@5049.49,4550.51 5125.51,4550.51 5265,4690 v3(5350,4690)
  Top Layer w16: C107.1@2794.64,3089.57 2795,3089.21 v3(2795,3040)
  Top Layer w24: D6.1@4728.74,4545 4745,4528.74 v3(4745,4450) ; D6.1@4733.74,4530 D6.1@4738.27,4534.53 ; D6.1@4738.27,4554.53 4879.53,4554.53 C80.1@4885,4560 ; C80.1@4885,4554.53 4887.01,4552.52 5047.48,4552.52 5049.49,4550.51 R68.1@5050,4550
  Signal Layer 2 w16: v1(2045,4500) 4695,4500 v3(4745,4450) ; v3(2143.7,3050.2) 2143.7,3049.37 2153.07,3040 v3(2449.71,3040)
  Signal Layer 3 w10: v1(2045,4500) v1@2047.7,4497.3
  Signal Layer 3 w12: v3(5340,5140) 5340,4893.01 5338.71,4891.72 5338.71,4703.32 5350,4692.03 v3(5350,4690)
  Signal Layer 3 w16: v1(2045,4500) 2074.03,4529.03 2074.03,4764.03 2100,4790 2100,4900 J17.43@2050,4950 ; J17.43@2045,4955 J17.43@2050,4950 ; v1@2047.7,4497.3 2047.7,3146.19 v3(2143.7,3050.2) ; J19.2@2050,5250 J17.43@2050,4950
  Signal Layer 4 w16: v3(2449.71,3040) v3(2795,3040)
  Bottom Layer w11: 2789.08,3218.25 2790.63,3219.79 2790.63,3220.1 2800.16,3229.63 U1.19@2800.16,3307.6
  Bottom Layer w12: 2788.13,3190.12 2789.08,3191.08 2789.08,3218.25 ; R61.2@5265,5155 5322.29,5155 ; R61.2@5274.18,5155 5322.29,5155 ; v3(5340,5140) 5337.29,5140 5322.29,5155
  Bottom Layer w16: 2788.13,3190.12 2788.13,3152.35 C13.1@2770.19,3134.41 2784.43,3120.17 2784.43,3090.69 2795,3080.12 v3(2795,3040)
  Bottom Layer w24: D1.2@2750.12,3040 v3(2795,3040) D2.2@2845,3040 ; R61.2@5264.53,5155 R61.2@5274.18,5164.65
V12: C4.1 C20.1 C21.1 C28.1 C29.1 C31.2 C54.1 C55.1 C68.1 C69.1 C70.1 C71.1 C104.1 C105.1 J1.3 J9.1 R21.4 R32.3 R45.2 R78.1 T2.1 TP4.1 | length 5198.2
  Top Layer w10: C4.1@1979.53,4735 v3@2115,4735 ; v3(3175,4235) 3187.56,4222.44 R78.1@3187.56,4185.4 ; R78.1@3187.56,4185 R78.1@3187.56,4185.4 ; TP4.1@3240.16,4220.67 3240.16,4208.37 3217.18,4185.4 R78.1@3187.56,4185.4
  Signal Layer 2 w10: v3(2100,4240) 2105,4235 v3(3175,4235) ; v3@3185,3600 3185,3565 3200,3550 J1.3@3650,3550
  Signal Layer 3 w10: v3(2100,4240) 2100,4425 2150,4475 2150,4700 2113.92,4736.08 v3@2113.92,4738.92 ; v3(3175,4235) 3175,4233 3165.14,4223.14 3165.14,4024.86 3185,4005 v3(3185,3605)
  Signal Layer 4 w24: v9@3227.22,1552.2 3394.5,1719.49 3394.5,2929.5 3650,3185 J1.3@3650,3550
  other v2: 3400,95 3440,95 3480,95 3520,95 3560,95 3600,95 3650,95 3690,95 3730,95 3770,95 3810,95 3850,95 3400,135 3440,135 3480,135 3520,135 3560,135 3600,135 3650,135 3690,135 3730,135 3770,135 3810,135 3850,135 3400,175 3440,175 3480,175 3520,175 3560,175 3600,175 3650,175 3690,175 3730,175 3770,175 3810,175 3850,175 3400,215 3440,215 3480,215 3520,215 3560,215 3600,215 3650,215 3690,215 3730,215 3770,215 3810,215 3850,215 3400,701.27 3850,701.27 3400,741.27 3850,741.27 3400,781.27 3440,781.27 3480,781.27 3770,781.27 3810,781.27 3850,781.27
  other v3: 2110,4740
  other v9: 3225,1555
V12SNS: C38.1 J17.3 R45.1 R49.2 U1.36 | length 3617.6
  Top Layer w10: R45.1@2055,4680.47 2110.47,4680.47 v3(2120,4690)
  Signal Layer 2 w8: v3@2605,4720 3320,4720 3330,4710 v3(4000,4710)
  Signal Layer 2 w10: v3(2120,4690) 2150,4720 v3(2600,4720) v3@2605,4720
  Signal Layer 3 w8: v3(2600,4720) 2622.87,4697.13 2622.87,4160.89 2620.56,4158.58 2620.56,4110 2615.87,4105.31 2615.87,3862.33 2605,3851.46 v3(2605,3600) ; v3(4000,4710) 4000,4900 J17.3@4050,4950
  Bottom Layer w8: 2462.56,3600 v3(2605,3600)
  Bottom Layer w9.8: v3(2605,3600) 2605,3584.01 2610.74,3578.27 U1.36@2647.6,3578.27
  Bottom Layer w10: C38.1@2460,3610 2462.56,3607.44 2462.56,3605 2462.56,3598.11 R49.2@2462.56,3560
V48: C6.1 C18.1 C22.1 C23.1 C24.1 C25.1 C26.1 C27.1 C32.1 C50.1 C51.1 C52.1 C53.1 C56.1 C57.1 C58.1 C59.1 C60.1 C61.1 C63.1 C64.1 C66.1 C67.1 D7.2 J1.1 J8.1 J41.2 Q1.4 Q4.4 Q10.4 Q13.4 R77.2 R88.2 T1.1 TP1.1 U1.13 U1.24 | length 8138.5
  Top Layer w16: v3(1325,4190) 1368.62,4190 1394.09,4215.47 R88.2@1400,4215.47 ; TP1.1@2252.8,4184.57 2253.02,4184.78 2294.78,4184.78 v3(2295,4185) R77.2@2332.44,4185
  Top Layer w24: v3(5432.98,3872.56) D7.2@5432.98,3961.87 5435,3963.89 J41.2@5435,4097.06
  Signal Layer 2 w16: v3(415,4190) 2288.38,4190 2293.38,4185 v3(2295,4185) ; v3(2660,3265) 2675.45,3280.45 2959.55,3280.45 v3(2980,3260) 3096.29,3260 3101.29,3265 v3(3740,3265)
  Signal Layer 3 w16: v1@370,2785 415,2830 v3(415,4190) ; v3(3740,3265) 3851.1,3376.1 J1.1@3850,3550
  Signal Layer 3 w24: v1(5335,2790) 5510,2965 5510,3795.54 v3(5432.98,3872.56)
  Signal Layer 4 w24: J1.1@3855,3550 4525,3550 4915,3160 v1(4915,2790)
  Bottom Layer w10: v3(2660,3265) 2691.33,3265 2701.73,3275.4 U1.24@2701.73,3307.6 ; U1.13@2918.27,3307.6 2917.99,3307.32 2917.99,3274.91 2926.11,3266.78 2954.74,3266.78 2961.52,3260 v3(2980,3260)
  Bottom Layer w16: v3(3102.91,3265) 3104.54,3265 3109.98,3259.56 3131.82,3259.56 3145.47,3245.91 C6.1@3145.47,3240
  other v1: 165,985 235,985 305,985 570,988.24 640,988.24 710,988.24 4900,1000 4970,1000 5040,1000 5300,1000 5370,1000 5440,1000 400,1300 470,1300 540,1300 5060,1300 5130,1300 5200,1300 400,1370 470,1370 540,1370 5060,1370 5130,1370 5200,1370 400,1440 470,1440 540,1440 5060,1440 5130,1440 5200,1440 400,1510 470,1510 540,1510 5060,1510 5130,1510 5200,1510 400,1580 470,1580 540,1580 5060,1580 5130,1580 5200,1580 400,1650 470,1650 540,1650 5060,1650 5130,1650 5200,1650 400,1720 470,1720 540,1720 5060,1720 5130,1720 5200,1720 220,2785 290,2785 360,2785 430,2785 500,2785 570,2785 640,2785 710,2785 4985,2790 5055,2790 5125,2790 5195,2790 5265,2790
  other v2: 1025,95 1065,95 1105,95 1145,95 1185,95 1225,95 1275,95 1315,95 1355,95 1395,95 1435,95 1475,95 1025,135 1065,135 1105,135 1145,135 1185,135 1225,135 1275,135 1315,135 1355,135 1395,135 1435,135 1475,135 1025,175 1065,175 1105,175 1145,175 1185,175 1225,175 1275,175 1315,175 1355,175 1395,175 1435,175 1475,175 1025,215 1065,215 1105,215 1145,215 1185,215 1225,215 1275,215 1315,215 1355,215 1395,215 1435,215 1475,215 1025,701.27 1475,701.27 1025,741.27 1475,741.27 1025,781.27 1065,781.27 1105,781.27 1395,781.27 1435,781.27 1475,781.27
  other v4: 352.7,1854.45 422.7,1854.45 492.7,1854.45 562.7,1854.45 5040,1855 5110,1855 5180,1855 5250,1855 352.7,1924.45 422.7,1924.45 492.7,1924.45 562.7,1924.45 5040,1925 5110,1925 5180,1925 5250,1925 352.7,1994.45 422.7,1994.45 492.7,1994.45 562.7,1994.45 5040,1995 5110,1995 5180,1995 5250,1995 352.7,2064.45 422.7,2064.45 492.7,2064.45 562.7,2064.45 5040,2065 5110,2065 5180,2065 5250,2065 352.7,2134.45 422.7,2134.45 492.7,2134.45 562.7,2134.45 5040,2135 5110,2135 5180,2135 5250,2135 352.7,2204.45 422.7,2204.45 492.7,2204.45 562.7,2204.45 5040,2205 5110,2205 5180,2205 5250,2205 354.19,2349.37 424.19,2349.37 494.19,2349.37 564.19,2349.37 5040,2355 5110,2355 5180,2355 5250,2355 354.19,2419.37 424.19,2419.37 494.19,2419.37 564.19,2419.37 5040,2425 5110,2425 5180,2425 5250,2425 354.19,2489.37 424.19,2489.37 494.19,2489.37 564.19,2489.37 5040,2495 5110,2495 5180,2495 5250,2495 354.19,2559.37 424.19,2559.37 494.19,2559.37 564.19,2559.37 5040,2565 5110,2565 5180,2565 5250,2565 354.19,2629.37 424.19,2629.37 494.19,2629.37 564.19,2629.37 5040,2635 5110,2635 5180,2635 5250,2635 354.19,2699.37 424.19,2699.37 494.19,2699.37 564.19,2699.37 5040,2705 5110,2705 5180,2705 5250,2705
V48SNS: C96.1 J17.1 R88.1 R100.2 U3.1 | length 3549.2
  Top Layer w9: C96.1@1340,4340 1342.76,4342.76 U3.1@1472.6,4342.76 ; R100.2@1400,4340 R88.1@1400,4274.53 1464.53,4274.53 v3(1465,4275)
  Signal Layer 2 w9: v3(1465,4275) 2285,4275 2310,4300 3670,4300 3701.27,4331.27 3701.27,4338.73 3700,4340 3700,4389.73 3715.27,4405 4085,4405 v3(4100,4420)
  Signal Layer 3 w9: v3(4100,4420) 4100,4900 4145,4945 J17.1@4145,4955
VCCB: C74.2 R107.1 U5.2 | length 150
  Top Layer w8: R107.1@5134.09,5068.07 5134.09,5028.46 C74.2@5137.56,5025
  Top Layer w9.8: C74.2@5130,5015 5170,5015 5195.31,4989.69 U5.2@5225,4989.69
VREF: C75.1 R11.2 R46.1 R89.1 U1.1 | length 2347.6
  Top Layer w10: v7(1725.85,4379.67) 1725.85,4377.64 1757.94,4345.54 R89.1@1757.94,4338.3 ; R11.2@3015,3667.44 3017.44,3665 v3(3060,3665)
  Signal Layer 2 w10: v7(1725.85,4379.67) 1780.48,4379.67 1798.66,4397.85 v7(2984.71,4397.85)
  Signal Layer 3 w10: v7(2984.71,4397.85) 2984.71,4394.06 2991.57,4387.2 2991.57,4386.52 2997.56,4380.53 2997.56,3727.44 v3(3060,3665)
  Bottom Layer w10: U1.1@2972.4,3578.27 3001.32,3578.27 3008.35,3585.3 3008.35,3594.93 3030,3615 C75.1@3062.44,3615 3062.44,3662.56 v3(3060,3665) R46.1@3115,3665
VSET: C12.1 R46.2 R50.2 R64.2 U1.48 | length 405.7
  Bottom Layer w9.8: U1.48@2918.27,3632.4 U1.48@2918.27,3637.32 2918.27,3666.3 2934.53,3682.57 3022.57,3682.57 3085,3745 C12.1@3085,3755.55
  Bottom Layer w10: C12.1@3085,3755.55 3091.26,3761.81 R50.2@3138.39,3761.81 ; R46.2@3115,3722.56 3115.98,3722.56 3126.73,3733.31 3126.73,3734.29 3128.27,3735.83 3128.27,3751.69 R50.2@3138.39,3761.81 ; R64.2@3194.78,3761.81 R50.2@3138.39,3761.81
pads on no net: FID1.1 FID2.1 FID3.1 FID4.1 FID5.1 FID6.1 H1.1 H2.1 H3.1 H4.1 H5.0 H6.0 H7.0 H8.0 J17.59 J18.1 J18.3 J18.25 J18.31 J18.33 J18.47 J18.49 J18.51 J18.53 J18.55 J18.57 J18.59 J31.1 J31.2 J31.3 J31.4 J31.7 J31.8 L1.MP L2.MP U4.1 U5.11 U6.5 U6.6 U7.5 U7.6 U8.5 U8.6 U9.5 U9.6
copper on no net:
  other v1: 2495,90 2565,90 2635,90 2730,90 2800,90 2870,90 2965,90 3035,90 3105,90 3950,1710 4450,1710
  other v3: 1995,3500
